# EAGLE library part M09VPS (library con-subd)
SUB-D
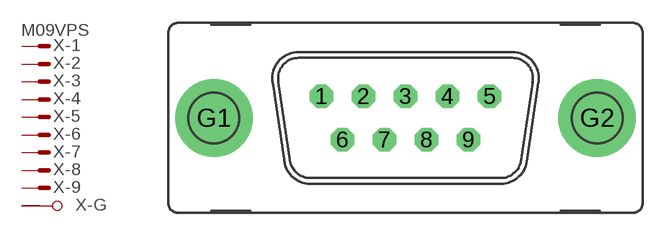
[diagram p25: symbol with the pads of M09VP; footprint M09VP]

Designator prefix X; gates -2=M -3=M -4=M -5=M -6=M -7=M -8=M -9=M -G=GND -1=MV

## M09VPS (OC_FARNELL: unknown; OC_NEWARK: unknown)  [M09VP]
1  -1:M  pas
2  -2:M  pas
3  -3:M  pas
4  -4:M  pas
5  -5:M  pas
6  -6:M  pas
7  -7:M  pas
8  -8:M  pas
9  -9:M  pas
G1  -G:G1  pas
G2  -G:G2  pas

## Footprint M09VP (pad centres in mm)
SUB-D
drill 1.016 octagon: 1 -5.486,1.422; 2 -2.743,1.422; 3 0,1.422; 4 2.743,1.422; 5 5.486,1.422; 6 -4.115,-1.422; 7 -1.372,-1.422; 8 1.372,-1.422; 9 4.115,-1.422
drill 3.302 pad 5.08 round: G1 -12.522,0; G2 12.522,0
